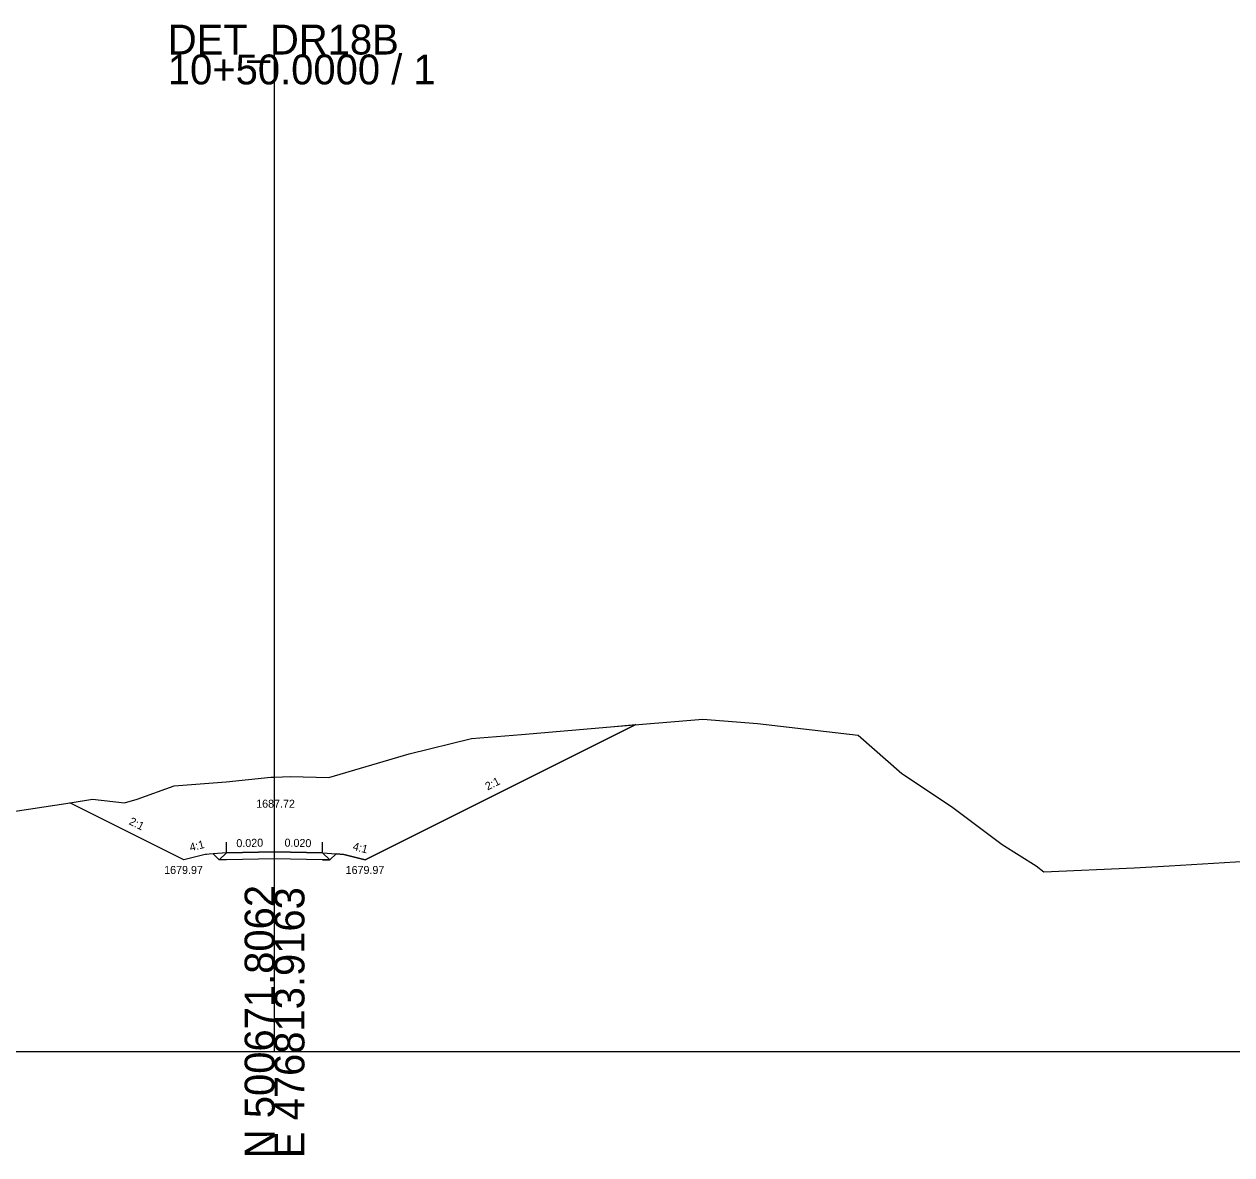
# Model space of a CAD drawing. Extents: x -26 to 403, y -10 to 2570.
# Drawn here: x 176.5 to 289.7, y 990.3 to 1096.3 of the extents above; entities that cross this region are included whole.
import ezdxf

# ---------------------------------------------------------------- set-up
doc = ezdxf.new("R2010")
doc.units = 0
for name, color, linetype in [('Exist Cross Section Cell', 7, 'Continuous'), ('Exist XS Center Line Elevation Label', 7, 'Continuous'), ('Exist XS Ground Line', 7, 'Continuous'), ('Prop XS Ditch Slope Text', 7, 'Continuous'), ('Prop XS Ditch Standard Text', 7, 'Continuous'), ('Prop XS Dump Level', 7, 'Continuous'), ('Prop XS Earthwork Shape', 7, 'Continuous'), ('Prop XS EOT Tick Mark', 7, 'Continuous'), ('Prop XS Finish Grade', 7, 'Continuous'), ('Prop XS Finish Grade Earthwork', 7, 'Continuous'), ('Prop XS Finish Grade Pavement', 7, 'Continuous'), ('Prop XS Hydro Typical Ditch Data', 7, 'Continuous'), ('Prop XS Pvmt Edge Slope', 7, 'Continuous'), ('Prop XS SE Text', 7, 'Continuous'), ('Prop XS Shoulder Borrow Shape', 7, 'Continuous'), ('Prop XS Side Slope Text', 7, 'Continuous'), ('Prop XS Subgrade Earthwork', 7, 'Continuous')]:
    doc.layers.add(name, color=color, linetype=linetype)

msp = doc.modelspace()

# ---------------------------------------------------------------- linework, layer by layer
at = {"layer": 'Exist Cross Section Cell'}
for p, q in [((200, 1000), (200, 1093.46)), ((0, 1000), (200, 1000)), ((200, 1000), (400, 1000))]:
    msp.add_line(p, q, dxfattribs=at)
at = {"layer": 'Exist XS Ground Line'}
msp.add_lwpolyline([(158.22, 1019.88), (180.85, 1023.31), (182.93, 1023.64), (185.93, 1023.3), (187.13, 1023.64), (190.59, 1024.89), (195.48, 1025.29), (199.64, 1025.71), (200, 1025.72), (201.48, 1025.78), (205.08, 1025.67), (212.62, 1027.91), (218.45, 1029.33), (223.13, 1029.71), (231.46, 1030.44), (240.12, 1031.15), (245.24, 1030.74), (254.67, 1029.66), (258.76, 1026.05), (263.42, 1022.97), (268.16, 1019.39), (271.37, 1017.39), (272.09, 1016.83), (280.55, 1017.23), (283.84, 1017.41), (292.09, 1017.91)], dxfattribs=at)
at = {"layer": 'Prop XS Dump Level'}
for p, q in [((200, 1018.72), (195.5, 1018.63)), ((195.5, 1018.63), (200, 1018.72)), ((204.5, 1018.63), (200, 1018.72)), ((200, 1018.72), (204.5, 1018.63))]:
    msp.add_line(p, q, dxfattribs=at)
at = {"layer": 'Prop XS Earthwork Shape'}
msp.add_lwpolyline([(204.5, 1017.96), (200, 1018.05), (195.5, 1017.96), (194.82, 1017.95), (194.24, 1018.53), (193.5, 1018.47), (191.5, 1017.97), (180.82, 1023.3), (180.85, 1023.31), (182.93, 1023.64), (185.93, 1023.3), (187.13, 1023.64), (190.59, 1024.89), (195.48, 1025.29), (199.64, 1025.71), (200, 1025.72), (201.48, 1025.78), (205.08, 1025.67), (212.62, 1027.91), (218.45, 1029.33), (223.13, 1029.71), (231.46, 1030.44), (233.84, 1030.64), (208.5, 1017.97), (206.5, 1018.47), (205.76, 1018.53), (205.18, 1017.95)], close=True, dxfattribs=at)
at = {"layer": 'Prop XS EOT Tick Mark'}
for p, q in [((195.5, 1018.63), (195.5, 1019.63)), ((204.5, 1018.63), (204.5, 1019.63))]:
    msp.add_line(p, q, dxfattribs=at)
at = {"layer": 'Prop XS Finish Grade'}
for p, q in [((195.5, 1018.63), (194.24, 1018.53)), ((204.5, 1018.63), (205.76, 1018.53))]:
    msp.add_line(p, q, dxfattribs=at)
at = {"layer": 'Prop XS Finish Grade Earthwork'}
for p, q in [((208.5, 1017.97), (233.84, 1030.64)), ((191.5, 1017.97), (180.82, 1023.3)), ((193.5, 1018.47), (191.5, 1017.97)), ((194.24, 1018.53), (193.5, 1018.47)), ((205.76, 1018.53), (206.5, 1018.47)), ((206.5, 1018.47), (208.5, 1017.97))]:
    msp.add_line(p, q, dxfattribs=at)
at = {"layer": 'Prop XS Finish Grade Pavement'}
for p, q in [((195.5, 1018.63), (200, 1018.72)), ((200, 1018.72), (204.5, 1018.63))]:
    msp.add_line(p, q, dxfattribs=at)
at = {"layer": 'Prop XS Hydro Typical Ditch Data'}
for p, q in [((208.5, 1017.97), (233.84, 1030.64)), ((191.5, 1017.97), (180.82, 1023.3)), ((193.5, 1018.47), (191.5, 1017.97)), ((206.5, 1018.47), (208.5, 1017.97))]:
    msp.add_line(p, q, dxfattribs=at)
at = {"layer": 'Prop XS Pvmt Edge Slope'}
for p, q in [((195.5, 1018.63), (194.82, 1017.95)), ((204.5, 1018.63), (205.18, 1017.95))]:
    msp.add_line(p, q, dxfattribs=at)
at = {"layer": 'Prop XS Shoulder Borrow Shape'}
for points in [[(195.5, 1018.63), (194.24, 1018.53), (194.82, 1017.95)], [(204.5, 1018.63), (205.76, 1018.53), (205.18, 1017.95)]]:
    msp.add_lwpolyline(points, close=True, dxfattribs=at)
at = {"layer": 'Prop XS Subgrade Earthwork'}
for p, q in [((194.82, 1017.95), (194.24, 1018.53)), ((205.18, 1017.95), (205.76, 1018.53)), ((195.5, 1017.96), (194.82, 1017.95)), ((200, 1018.05), (195.5, 1017.96)), ((204.5, 1017.96), (200, 1018.05)), ((204.5, 1017.96), (205.18, 1017.95))]:
    msp.add_line(p, q, dxfattribs=at)

# ---------------------------------------------------------------- texts
at = {"layer": 'Exist Cross Section Cell'}
for s, p in [('DET_DR18B', (190, 1093.46)), ('10+50.0000 / 1', (190, 1090.66))]:
    msp.add_text(s, height=2.8, dxfattribs=at).set_placement(p)
for s, p in [('N 500671.8062', (200, 990)), ('E 476813.9163', (202.8, 990))]:
    msp.add_text(s, height=2.8, rotation=90, dxfattribs=at).set_placement(p)
at = {"layer": 'Exist XS Center Line Elevation Label'}
msp.add_text('1687.72', height=0.75, dxfattribs=at).set_placement((198.28, 1022.85))
at = {"layer": 'Prop XS Ditch Slope Text'}
for rotation, p in [(14.0362, (192.14, 1018.75)), (345.9638, (207.28, 1018.9))]:
    msp.add_text('4:1', height=0.75, rotation=rotation, dxfattribs=at).set_placement(p)
at = {"layer": 'Prop XS Ditch Standard Text'}
for p in [(189.66, 1016.64), (206.66, 1016.64)]:
    msp.add_text('1679.97', height=0.75, dxfattribs=at).set_placement(p)
at = {"layer": 'Prop XS Dump Level'}
for p in [(193.5, 1018.43), (206.5, 1018.43)]:
    msp.add_text('Case1', height=0.04, dxfattribs=at).set_placement(p)
at = {"layer": 'Prop XS SE Text'}
for rotation, p in [(1.1458, (196.43, 1019.15)), (358.8542, (200.93, 1019.2))]:
    msp.add_text('0.020', height=0.75, rotation=rotation, dxfattribs=at).set_placement(p)
at = {"layer": 'Prop XS Side Slope Text'}
for rotation, p in [(26.5651, (219.96, 1024.46)), (333.4349, (186.3, 1021.33))]:
    msp.add_text('2:1', height=0.75, rotation=rotation, dxfattribs=at).set_placement(p)

doc.saveas('drawing.dxf')
